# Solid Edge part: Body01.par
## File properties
Author: ptcarter
Template: ANSIMM.PAR
Last saved by: ptcarter
Revision: 50
Application: Solid Edge
Accuracy: 0.99
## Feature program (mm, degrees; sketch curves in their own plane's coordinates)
sketch for "unnamed Protrusion 1" plane through (0, 0, 0) normal (0, -1, 0) x-axis (1, 0, 0)
  circle centre (0, 0) radius 35
extrude "unnamed Protrusion 1" add finite 70 symmetric
sketch for "unnamed Protrusion 2" plane through (0, -35, 0) normal (0, -1, 0) x-axis (1, 0, 0)
  line (-35, -45) -> (35, -45)
  arc centre (35, -35) radius 10 from (35, -45) to (45, -35) ccw
  line (45, -35) -> (45, 35)
  arc centre (35, 35) radius 10 from (45, 35) to (35, 45) ccw
  line (35, 45) -> (-35, 45)
  arc centre (-35, 35) radius 10 from (-35, 45) to (-45, 35) ccw
  line (-45, 35) -> (-45, -35)
  arc centre (-35, -35) radius 10 from (-45, -35) to (-35, -45) ccw
extrude "unnamed Protrusion 2" add finite 10 along -normal
mirror "unnamed Mirror 1" of "unnamed Protrusion 2" about plane through (0, 0, 0) normal (0, -1, 0)
extrude "unnamed Protrusion 3" add finite 10
sketch for "Hole_1" plane through (0, -35, 0) normal (0, -1, 0) x-axis (1, 0, 0)
  hole centre (-35, -35) bore radius 4
hole "Hole_1" through
sketch for "Hole_2" plane through (0, -35, 0) normal (0, -1, 0) x-axis (1, 0, 0)
  hole centre (35, -35) bore radius 4
hole "Hole_2" through
sketch for "Hole_3" plane through (0, -35, 0) normal (0, -1, 0) x-axis (1, 0, 0)
  hole centre (35, 35) bore radius 4
hole "Hole_3" through
sketch for "Hole_4" plane through (0, -35, 0) normal (0, -1, 0) x-axis (1, 0, 0)
  hole centre (-35, 35) bore radius 4
hole "Hole_4" through
pattern "unnamed Pattern 1" of "Hole_1", "Hole_2", "Hole_3", "Hole_4"
sketch for "unnamed Protrusion 4" plane through (0, -25, 0) normal (0, 1, 0) x-axis (1, 0, 0)
  line (24.4949, 25) -> (37, 25)
  line (37, 25) -> (37, -25)
  line (37, -25) -> (24.4949, -25)
extrude "unnamed Protrusion 4" add through along +normal
sketch for "unnamed Protrusion 5" plane through (0, 0, 0) normal (0, 0, 1) x-axis (1, 0, 0)
  circle centre (0, 0) radius 16
extrude "unnamed Protrusion 5" add finite 83 along +normal
sketch for "unnamed Protrusion 6" plane through (0, 0, 83) normal (0, 0, 1) x-axis (1, 0, 0)
  line (-20, -30) -> (20, -30)
  arc centre (20, -20) radius 10 from (30, -20) to (20, -30) cw
  line (30, -20) -> (30, 20)
  arc centre (20, 20) radius 10 from (20, 30) to (30, 20) cw
  line (20, 30) -> (-20, 30)
  arc centre (-20, 20) radius 10 from (-30, 20) to (-20, 30) cw
  line (-30, 20) -> (-30, -20)
  arc centre (-20, -20) radius 10 from (-20, -30) to (-30, -20) cw
extrude "unnamed Protrusion 6" add finite 10 along -normal
fillet "unnamed Round 1"
sketch for "Hole_5" plane through (0, 0, 73) normal (0, 0, -1) x-axis (1, 0, 0)
hole "Hole_5" through
sketch for "Hole_6" plane through (0, 0, 73) normal (0, 0, -1) x-axis (1, 0, 0)
hole "Hole_6" through
sketch for "Hole_7" plane through (0, 0, 73) normal (0, 0, -1) x-axis (1, 0, 0)
hole "Hole_7" through
sketch for "Hole_8" plane through (0, 0, 73) normal (0, 0, -1) x-axis (1, 0, 0)
  hole centre (20, 20) bore radius 4
hole "Hole_8" through
pattern "unnamed Pattern 2" of "Hole_5", "Hole_6", "Hole_7", "Hole_8"
fillet "unnamed Round 2"
sketch for "Hole_9" plane through (0, -35, 0) normal (0, -1, 0) x-axis (1, 0, 0)
hole "Hole_9" through
sketch for "Hole_10" plane through (0, 0, 0) normal (0, 0, 1) x-axis (1, 0, 0)
  hole centre (0, 0) bore radius 7.5
hole "Hole_10" through
sketch for "Hole_11" plane through (0, 0, 83) normal (0, 0, 1) x-axis (1, 0, 0)
hole "Hole_11" finite
sketch for "Hole_12" plane through (0, -35, 0) normal (0, -1, 0) x-axis (1, 0, 0)
hole "Hole_12" finite
chamfer "unnamed Chamfer 1"
mirror "unnamed Mirror 2" of "Hole_12" about plane through (0, 0, 0) normal (0, -1, 0)
hole "Hole_13" finite
chamfer "unnamed Chamfer 2"
rib "unnamed Rib 1"
mirror "unnamed Mirror 3" of "unnamed Rib 1" about plane through (0, 0, 0) normal (0, -1, 0)
rib "unnamed Rib 2"
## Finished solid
Body 1: solid body, 117 faces, 268 edges, 140 vertices.
  Faces by surface: cylinder 57, plane 30, torus 22, sphere 4, blend 2, cone 2
  Edges by curve: circle 139, line 112, intersection 17
Bounding box of the edges (mm; curved faces can reach further): 90.000 x 70.000 x 128.000, from (-45, -35, -45) to (45, 35, 83).
Cylindrical faces by radius (mm): R2 x14, R4 x22, R7.5 x1, R10 x13, R16 x2, R30 x1, R32.5 x2, R35 x2
Conical faces (half-angle, radius in mm at the cone's reference point): 45 deg R33.5 x2
Toroidal faces (ring radius, tube radius in mm): R8 r2 x12, R8 r4 x4, R20 r4 x2, R39 r4 x4
Spherical faces by radius (mm): R4 x4
Planar faces by outward normal: +x 6, +y 4, +z 5, -x 5, -y 4, -z 4, oblique 2
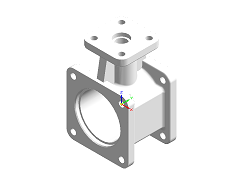
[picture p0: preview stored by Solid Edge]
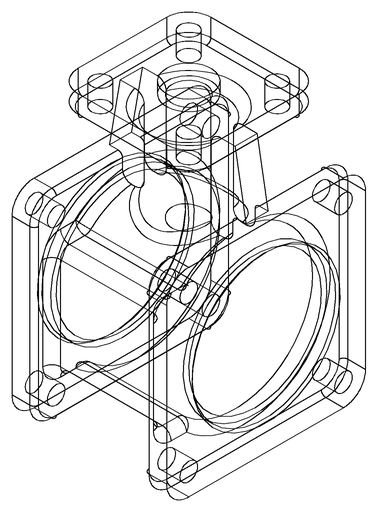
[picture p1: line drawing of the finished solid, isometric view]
